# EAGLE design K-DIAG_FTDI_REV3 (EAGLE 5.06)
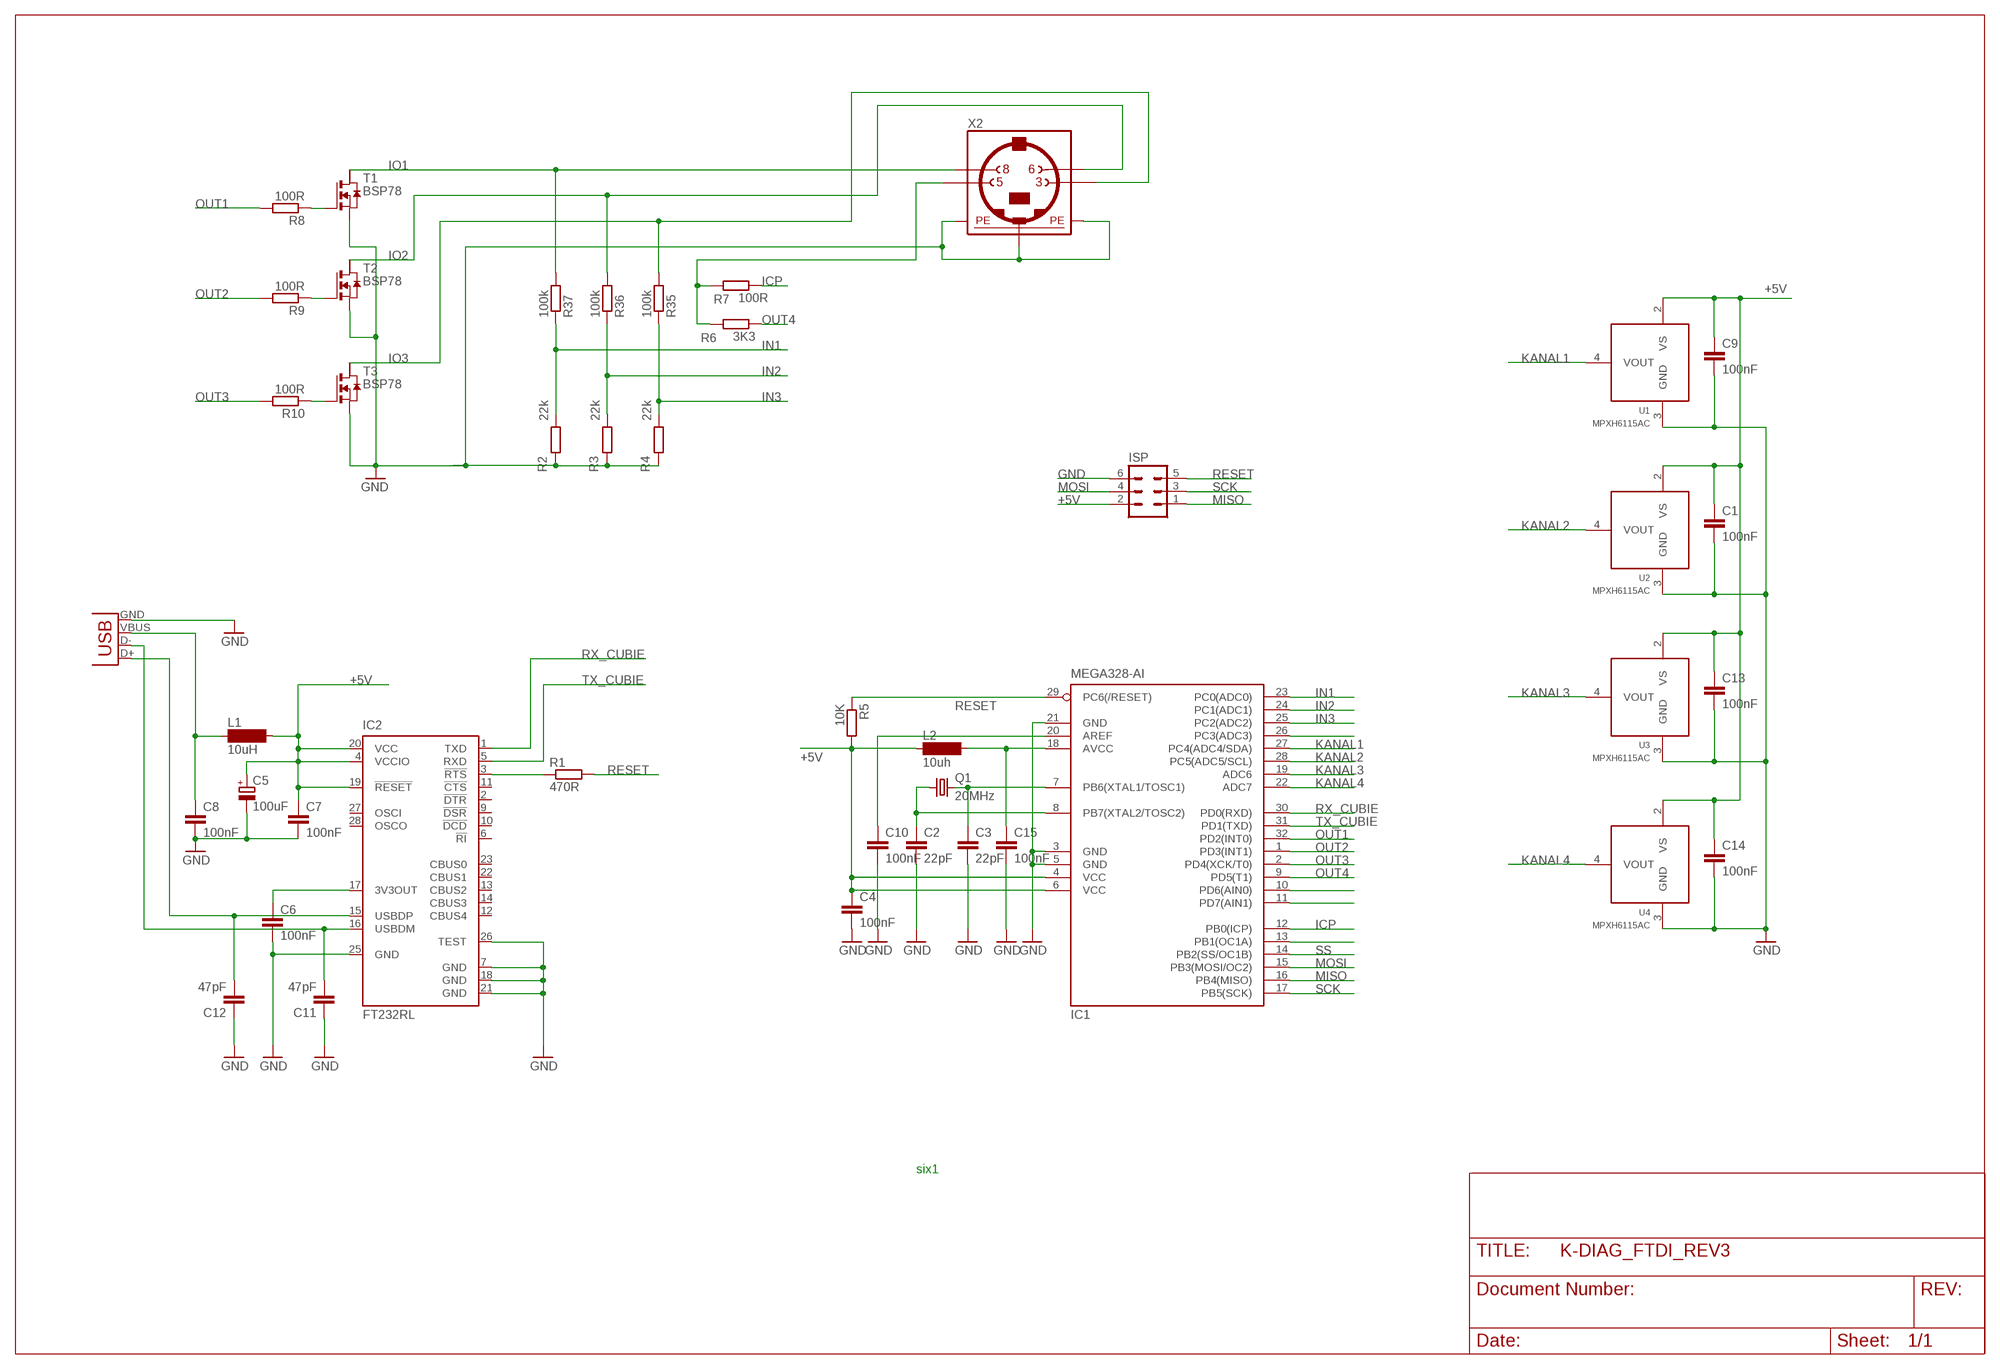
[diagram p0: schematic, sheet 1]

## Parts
C1  100nF  C-EUC0805  [C0805]
C2  22pF  C-EUC0805  [C0805]
C3  22pF  C-EUC0805  [C0805]
C4  100nF  C-EUC0805  [C0805]
C5  100uF  CPOL-EU153CLV-0605  [153CLV-0605]
C6  100nF  C-EUC0805  [C0805]
C7  100nF  C-EUC0805  [C0805]
C8  100nF  C-EUC0805  [C0805]
C9  100nF  C-EUC0805  [C0805]
C10  100nF  C-EUC0805  [C0805]
C11  47pF  C-EUC0805  [C0805]
C12  47pF  C-EUC0805  [C0805]
C13  100nF  C-EUC0805  [C0805]
C14  100nF  C-EUC0805  [C0805]
C15  100nF  C-EUC0805  [C0805]
IC1  MEGA328-AI  MEGA8-AI  [TQFP32-08]
IC2  FT232RL  [SSOP28]
ISP  ML6  [ML6]
L1  10uH  SM-1206  [SM-1206]
L2  10uh  SM-1206  [SM-1206]
Q1  20MHz  CRYSTAL10.5X4.8  [CRYSTAL-SMD-10.5X4.8-2PIN]
R1  470R  R-EU_R0805  [R0805]
R2  22k  R-EU_R0805  [R0805]
R3  22k  R-EU_R0805  [R0805]
R4  22k  R-EU_R0805  [R0805]
R5  10K  R-EU_R0805  [R0805]
R6  3K3  R-EU_R0805  [R0805]
R7  100R  R-EU_R0805  [R0805]
R8  100R  R-EU_R0805  [R0805]
R9  100R  R-EU_R0805  [R0805]
R10  100R  R-EU_R0805  [R0805]
R35  100k  R-EU_R0805  [R0805]
R36  100k  R-EU_R0805  [R0805]
R37  100k  R-EU_R0805  [R0805]
T1  BSP78  NMOSSOT223  [SOT223]
T2  BSP78  NMOSSOT223  [SOT223]
T3  BSP78  NMOSSOT223  [SOT223]
U1  MPXH6115AC  MPXH6400AC6T1  [SSOP8]
U2  MPXH6115AC  MPXH6400AC6T1  [SSOP8]
U3  MPXH6115AC  MPXH6400AC6T1  [SSOP8]
U4  MPXH6115AC  MPXH6400AC6T1  [SSOP8]
X1  USBPTH  [USB-B-PTH]
X2  MINI_DIN_4  [M_DIN4]

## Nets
+5V: C1.1 C4.1 C5.+ C7.1 C9.1 C13.1 C14.1 IC1.4(VCC) IC1.6(VCC) IC2.4(VCCIO) IC2.19(!RESET) IC2.20(VCC) ISP.2 L1.2 L2.1 R5.2 U1.2(VS) U2.2(VS) U3.2(VS) U4.2(VS)
GND: C1.2 C2.2 C3.2 C4.2 C5.- C6.2 C7.2 C8.2 C9.2 C10.2 C11.1 C12.1 C13.2 C14.2 C15.2 IC1.3(GND) IC1.5(GND) IC1.21(GND) IC2.7(GND) IC2.18(GND) IC2.21(GND) IC2.25(GND) IC2.26(TEST) ISP.6 R2.1 R3.1 R4.1 T1.3(S) T2.3(S) T3.3(S) U1.3(GND) U2.3(GND) U3.3(GND) U4.3(GND) X1.GND X2.SH1(PE1) X2.SH2(PE2) X2.SH3(PE3)
ICP: IC1.12(PB0(ICP)) R7.1
IN1: IC1.23(PC0(ADC0)) R2.2 R37.1
IN2: IC1.24(PC1(ADC1)) R3.2 R36.1
IN3: IC1.25(PC2(ADC2)) R4.2 R35.1
IN5: IC1.10(PD6(AIN0))
IN6: IC1.11(PD7(AIN1))
IN8: IC1.13(PB1(OC1A))
IO1: R37.2 T1.2(D) X2.8
IO2: R36.2 T2.2(D) X2.6
IO3: R35.2 T3.2(D) X2.3
KANAL1: IC1.27(PC4(ADC4/SDA)) U1.4(VOUT)
KANAL2: IC1.28(PC5(ADC5/SCL)) U2.4(VOUT)
KANAL3: IC1.19(ADC6) U3.4(VOUT)
KANAL4: IC1.22(ADC7) U4.4(VOUT)
MISO: IC1.16(PB4(MISO)) ISP.1
MOSI: IC1.15(PB3(MOSI/OC2)) ISP.4
N$1: C6.1 IC2.17(3V3OUT)
N$2: IC2.3(!RTS) R1.1
N$3: C8.1 L1.1 X1.VBUS
N$4: C10.1 IC1.20(AREF)
N$5: C15.1 IC1.18(AVCC) L2.2
N$6: C11.2 IC2.16(USBDM) X1.D-
N$7: R6.2 R7.2 X2.5
N$9: C2.1 IC1.8(PB7(XTAL2/TOSC2)) Q1.P$1
N$10: C3.1 IC1.7(PB6(XTAL1/TOSC1)) Q1.P$2
N$13: R8.1 T1.1(G)
N$19: C12.2 IC2.15(USBDP) X1.D+
N$33: R10.1 T3.1(G)
N$34: R9.1 T2.1(G)
OUT1: IC1.32(PD2(INT0)) R8.2
OUT2: IC1.1(PD3(INT1)) R9.2
OUT3: IC1.2(PD4(XCK/T0)) R10.2
OUT4: IC1.9(PD5(T1)) R6.1
REL4: IC1.26(PC3(ADC3))
RESET: IC1.29(PC6(/RESET)) ISP.5 R1.2 R5.1
RX_CUBIE: IC1.30(PD0(RXD)) IC2.1(TXD)
SCK: IC1.17(PB5(SCK)) ISP.3
SS: IC1.14(PB2(SS/OC1B))
TX_CUBIE: IC1.31(PD1(TXD)) IC2.5(RXD)
Unconnected: IC2.2(!DTR) IC2.6(!RI) IC2.9(!DSR) IC2.10(!DCD) IC2.11(!CTS) IC2.12(CBUS4) IC2.13(CBUS2) IC2.14(CBUS3) IC2.22(CBUS1) IC2.23(CBUS0) IC2.27(OSCI) IC2.28(OSCO) T1.4(D2) T2.4(D2) T3.4(D2) U1.1(NC) U1.5(NC) U1.6(NC) U1.7(NC) U1.8(NC) U2.1(NC) U2.5(NC) U2.6(NC) U2.7(NC) U2.8(NC) U3.1(NC) U3.5(NC) U3.6(NC) U3.7(NC) U3.8(NC) U4.1(NC) U4.5(NC) U4.6(NC) U4.7(NC) U4.8(NC)

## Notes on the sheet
- six1

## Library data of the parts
C1-C4 C6-C15 = rcl:C-EU: CAPACITOR, European symbol
C5 = rcl:CPOL-EU: POLARIZED CAPACITOR, European symbol
IC1 = atmel:MEGA8: MICROCONTROLLER 8 Kbytes FLASH, 1 kbytes SRAM, 512 bytes EEPROM, USART, 6-channel 10 bit ADC, 2-channel 8 bit ADC Pin compatible with Atmega48, ATMega88, ATMega168 Source: avr.lbr
IC2 = ftdichip:FT232R: Source: http://www.ftdichip.com/Documents/DataSheets/DS_FT232R_v104.pdf
ISP = con-harting-ml:ML6: HARTING
L1 L2 = inductor-neosid:SM-1206: INDUCTOR
Q1 = SparkFun:CRYSTAL: Crystals
R1-R10 R35-R37 = rcl:R-EU_: RESISTOR, European symbol
T1-T3 = zetex:NMOSSOT223: MOS FET
U1-U4 = mpxh6400:MPXH6400A
X1 = SparkFun:USB: USB Connectors USB-B-PTH is fully proven SKU : PRT-00139 USB-miniB is fully proven SKU : PRT-00587 USB-A-PCB is untested. USB-A-H is throughly reviewed, but untested. Spark Fun Electronics SKU : PRT-00437 USB-B-SMT is throughly reviewed, but untested. Needs silkscreen touching up. USB-A-S has not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
X2 = mini_din:MINI_DIN_4

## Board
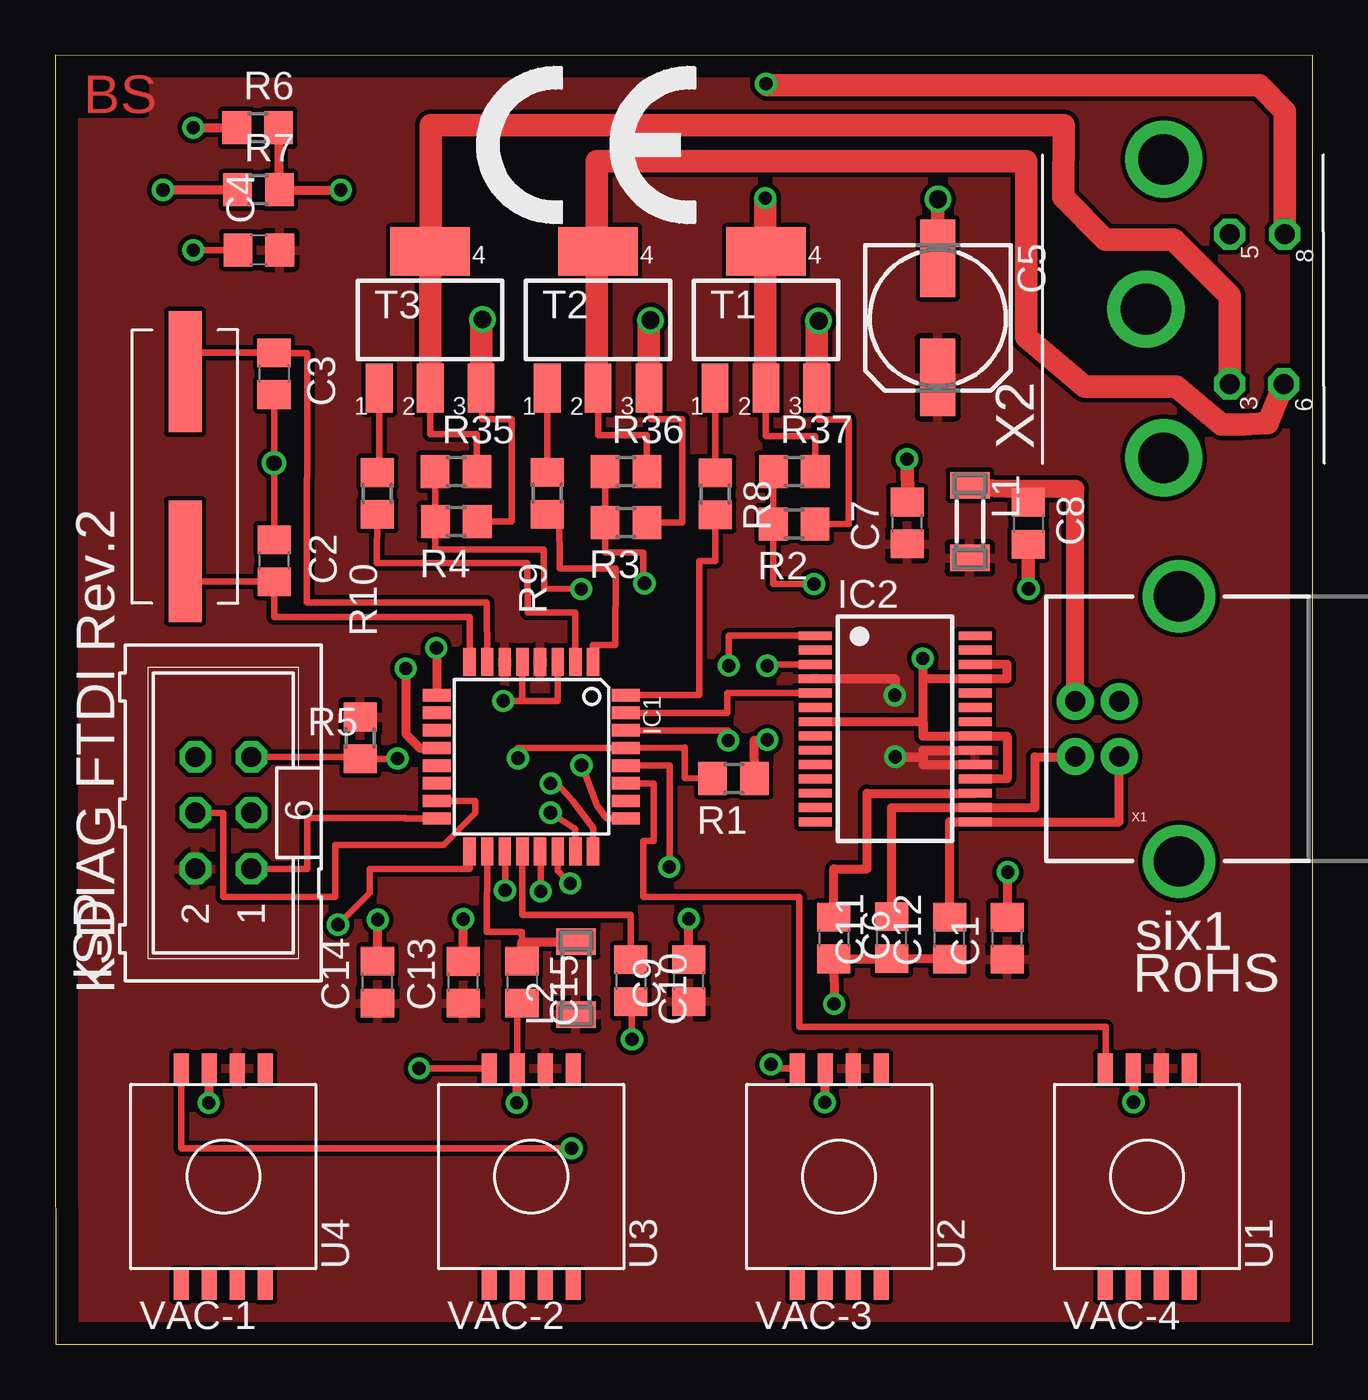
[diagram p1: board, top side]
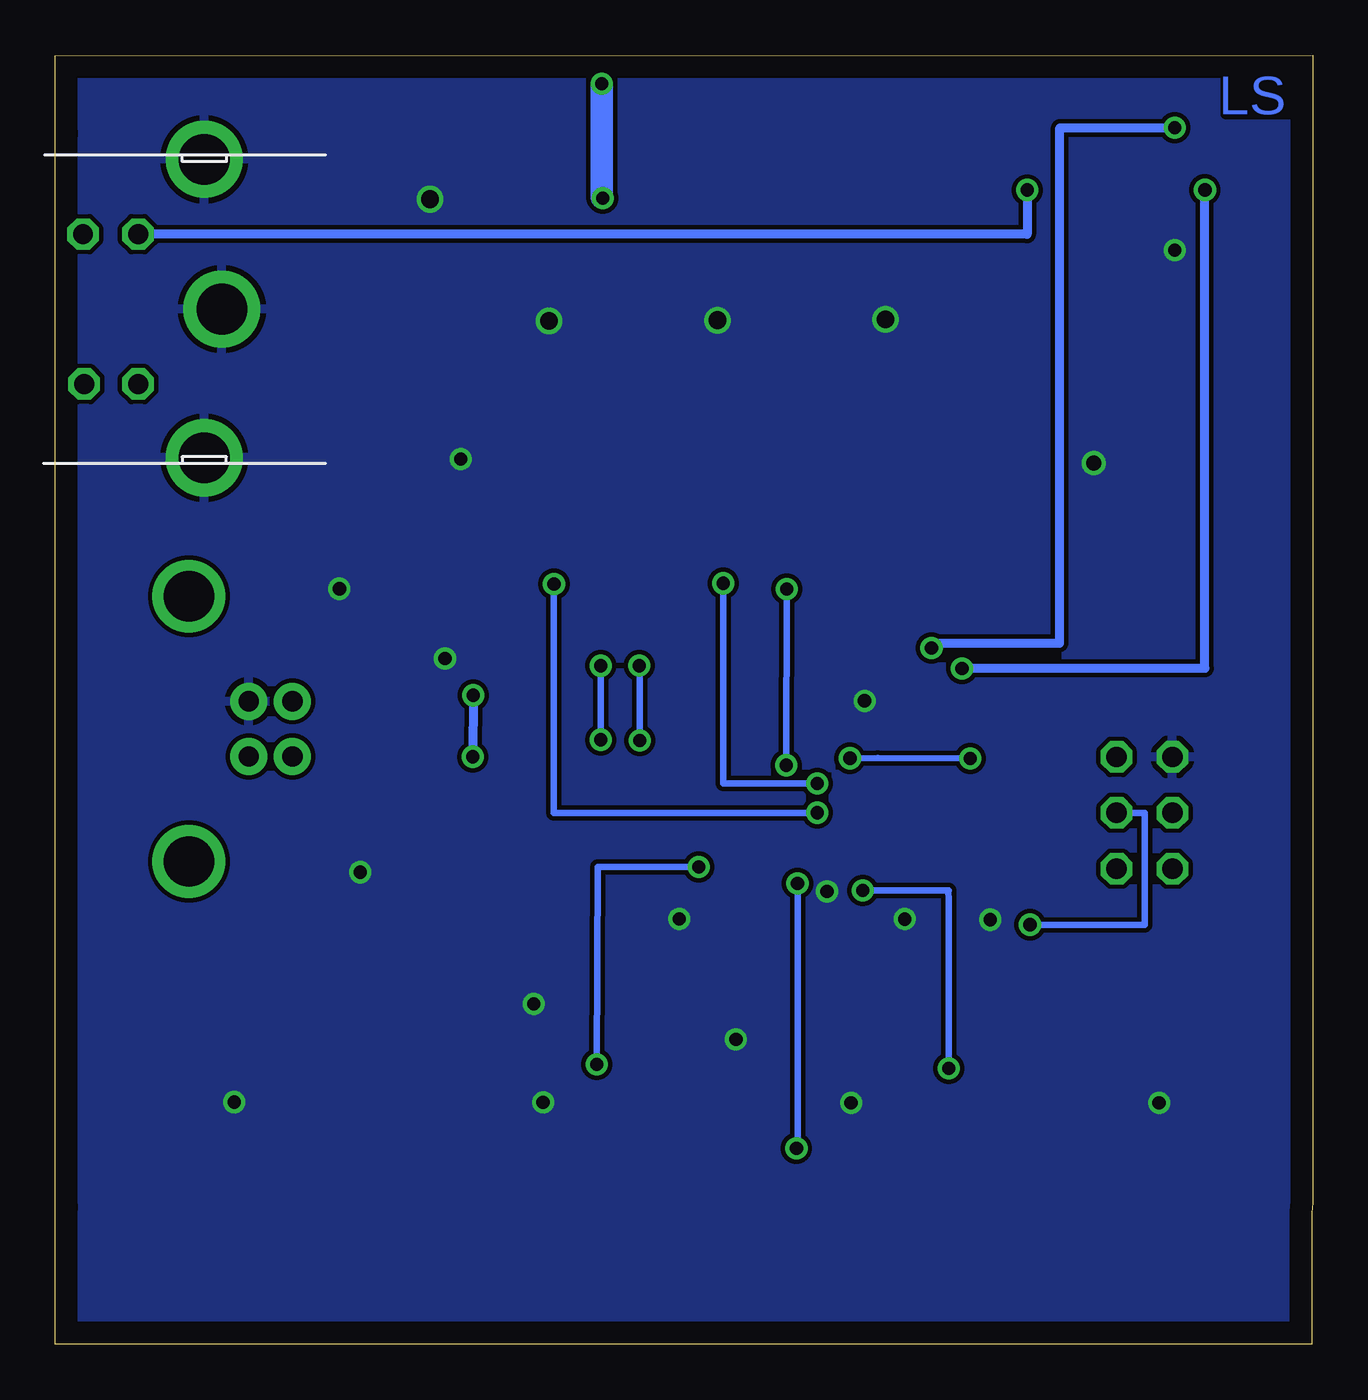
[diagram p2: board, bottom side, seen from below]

Size 57.06 x 58.52 mm. Coordinates in mm from the lower left corner, seen from the top.
Outline: 57.05,6.23 57.05,0 0.04,0 0.04,5.97 0,6.43 0,55.42 0,57.5 0,58.52 57.06,58.5 57.06,56.23 57.05,54.96 57.05,6.23
Outline: 57.05,6.23 57.05,6.23
Copper layers (1*16): Top 0.035mm / dielectric 1.5mm / Bottom 0.035mm
Design rules "default": minimum track width 10mil, minimum drill 24mil, track to track 8mil, track to pad 8mil, pad to pad 8mil, via to via 8mil, smd to smd 8mil, copper to edge 40mil, drill to drill 8mil, minimum pad ring 10mil, minimum via ring 8mil, stop-mask expansion 4mil, vias tented up to drill 0mil, thermal gap 10mil

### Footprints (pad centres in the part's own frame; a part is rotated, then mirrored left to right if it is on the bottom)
C0805 = smd 1.3 x 1.5: 1 -0.95,0; 2 0.95,0
153CLV-0605 = smd 3.5 x 1.6: + 2.7,0; - -2.7,0
TQFP32-08 = smd 1.27 x 0.559: 1 -4.293,2.8; 2 -4.293,2; 3 -4.293,1.2; 4 -4.293,0.4; 5 -4.293,-0.4; 6 -4.293,-1.2; 7 -4.293,-2; 8 -4.293,-2.8; 17 4.293,-2.8; 18 4.293,-2; 19 4.293,-1.2; 20 4.293,-0.4; 21 4.293,0.4; 22 4.293,1.2; 23 4.293,2; 24 4.293,2.8 | smd 0.559 x 1.27: 9 -2.8,-4.293; 10 -2,-4.293; 11 -1.2,-4.293; 12 -0.4,-4.293; 13 0.4,-4.293; 14 1.2,-4.293; 15 2,-4.293; 16 2.8,-4.293; 25 2.8,4.293; 26 2,4.293; 27 1.2,4.293; 28 0.4,4.293; 29 -0.4,4.293; 30 -1.2,4.293; 31 -2,4.293; 32 -2.8,4.293
SSOP28 = smd 0.4 x 1.5: 1 -4.225,-3.625; 2 -3.575,-3.625; 3 -2.925,-3.625; 4 -2.275,-3.625; 5 -1.625,-3.625; 6 -0.975,-3.625; 7 -0.325,-3.625; 8 0.325,-3.625; 9 0.975,-3.625; 10 1.625,-3.625; 11 2.275,-3.625; 12 2.925,-3.625; 13 3.575,-3.625; 14 4.225,-3.625; 15 4.225,3.625; 16 3.575,3.625; 17 2.925,3.625; 18 2.275,3.625; 19 1.625,3.625; 20 0.975,3.625; 21 0.325,3.625; 22 -0.325,3.625; 23 -0.975,3.625; 24 -1.625,3.625; 25 -2.275,3.625; 26 -2.925,3.625; 27 -3.575,3.625; 28 -4.225,3.625
ML6 = drill 0.914 octagon: 1 -2.54,-1.27; 2 -2.54,1.27; 3 0,-1.27; 4 0,1.27; 5 2.54,-1.27; 6 2.54,1.27
SM-1206 = smd 1.2 x 1.8: 1 -1.65,0; 2 1.65,0
CRYSTAL-SMD-10.5X4.8-2PIN = smd 5.5 x 1.5: P$1 -4.3,0; P$2 4.3,0
R0805 = smd 1.3 x 1.5: 1 -0.95,0; 2 0.95,0
SOT223 = smd 1.219 x 2.235: 1 -2.311,-3.099; 2 0,-3.099; 3 2.311,-3.099 | smd 3.6 x 2.2: 4 0,3.099
SSOP8 = smd 1.346 x 0.686: 1 4.915,-1.905; 2 4.915,-0.635; 3 4.915,0.635; 4 4.915,1.905; 5 -4.915,1.905; 6 -4.915,0.635; 7 -4.915,-0.635; 8 -4.915,-1.905
USB-B-PTH = drill 0.914 pad 1.676 round: D+ 0,1.25; D- 1.981,1.25; GND 0,-1.25; VBUS 1.981,-1.25 | drill 2.286 round: P$1 -2.718,-6.02; P$2 -2.718,6.02
M_DIN4 = drill 0.9 pad 1.422 octagon: 3 -3.4,-3.75; 5 3.4,-3.75; 6 -3.4,-6.2; 8 3.4,-6.25 | drill 2.3 pad 3.5 round: SH1 6.8,-0.75; SH2 0,0.05; SH3 -6.75,-0.75

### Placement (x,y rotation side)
C1  43.2,18.43 90 top
C2  9.95,35.57 90 top
C3  9.93,44.06 270 top
C4  9.24,49.67 180 top
C5  40.05,46.59 270 top
C6  35.33,18.45 270 top
C7  38.66,37.28 90 top
C8  44.16,37.27 270 top
C9  28.76,16.51 90 top
C10  26.12,16.51 270 top
C11  37.96,18.46 90 top
C12  40.58,18.44 90 top
C13  18.52,16.44 90 top
C14  14.63,16.44 90 top
C15  21.18,16.44 270 top
IC1  21.6,26.67 270 top
IC2  38.11,27.94 270 top
ISP  7.63,24.13 90 top
L1  41.5,37.35 270 top
L2  23.63,16.62 90 top
Q1  5.9,39.85 90 top
R1  30.78,25.69 180 top
R2  33.53,37.24 180 top
R3  25.9,37.31 180 top
R4  18.2,37.34 180 top
R5  13.85,27.53 90 top
R6  9.19,55.22 0 top
R7  9.22,52.4 0 top
R8  29.95,38.6 270 top
R9  22.32,38.63 270 top
R10  14.62,38.62 270 top
R35  18.19,39.61 0 top
R36  25.9,39.62 0 top
R37  33.54,39.62 0 top
T1  32.25,46.5 0 top
T2  24.63,46.5 0 top
T3  17.01,46.5 0 top
U1  49.54,7.62 90 top
U2  35.57,7.62 90 top
U3  21.6,7.62 90 top
U4  7.63,7.62 90 top
U$3  [CE_10.00]  19.06,50.8 0 top
X1  48.27,27.94 180 top
X2  49.54,46.99 90 top

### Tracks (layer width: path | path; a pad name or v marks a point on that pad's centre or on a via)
+5V  (via drill 0.6)
  Top 0.406: 39.38,26.96 IC2.20 | 39.38,26.96 39.38,26.32 IC2.19 | 39.38,26.96 39.38,26.67 v38.11,26.67 | v38.09,29.46 38.11,30.21 IC2.4
  Bottom 0.406: v38.09,29.46 v38.11,26.67
  pour Top: 64.78,60.33 29.22,60.33 27.93,60.22 -2.59,60.84 -2.53,16.51 -2.56,15.24 -2.56,-1.42 64.78,-1.27
GND  (via drill 0.6, 0.6 pad 0.81, 0.7, 0.8)
  Top 0.305: C3.2 v9.94,40 C2.2 | v22.04,20.56 22.04,22.38 IC1.21 | IC1.3 22.8,29.21 21.2,29.21 | 21.2,29.21 IC1.5 | v20.33,29.21 21.2,29.21 | C4.2 v6.27,49.67 | R4.1 20.72,37.34 20.72,42 19.39,42 v19.39,46.52 | R3.1 28.46,37.31 28.46,42 27.02,42 v27.02,46.49 | R2.1 36.02,37.24 36.02,41.98 34.65,41.98 v34.65,46.45 | C15.2 20.97,15.49 U3.3 | C10.2 26.17,15.56 v26.17,13.84
  Top 0.406: 39.38,27.61 IC2.21 43.19,27.61 43.19,25.66 IC2.18 | 39.38,30.21 IC2.25 43.19,30.21 43.19,30.86 IC2.26 | 39.38,27.61 39.38,30.21 | 39.38,27.61 39.38,28.27 IC2.7 | v35.34,15.46 35.33,17.4 C6.2 37.96,17.5 C11.1 40.58,17.51 C12.1 | 39.38,30.21 39.38,31.13 v39.37,31.13 | v43.22,21.43 43.22,19.38 C1.2 | v6.97,10.96 6.97,12.54 U4.3 | v20.95,10.96 20.95,12.54 U3.3 | v34.92,10.98 34.92,12.54 U2.3 | v48.93,10.99 48.93,12.54 U1.3 | C15.2 21.2,15.49 | v14.63,19.28 14.63,18.06 C14.2 | v18.52,19.3 C13.2 | v28.75,19.32 v28.76,19.32 C9.2
  Top 0.61: C7.2 38.69,38.18 v38.65,40.18 | C8.2 v44.16,34.29 | C5.- 40.05,50.14 v40.05,51.98
  Top 1.016: v34.65,46.45 34.57,46.37 T1.3 | v27.02,46.49 26.95,46.42 T2.3 | v19.39,46.52 19.33,46.46 T3.3
  pour Bottom: 64.78,60.33 26.68,60.33 26.66,60.22 27.89,60.15 -2.53,60.96 -2.56,16.51 -2.56,-1.34 64.78,-1.27
ICP  (via drill 0.6)
  Top 0.406: IC1.12 16.55,27.07 15.91,27.71 v15.91,30.68 | v4.89,52.4 R7.1
  Bottom 0.406: v15.91,30.68 4.89,30.68 v4.89,52.4
IN1  (via drill 0.6 pad 0.81)
  Top 0.305: IC1.23 23.6,23.4 v22.48,24.13 | v34.43,34.52 32.58,34.52 R2.2 R37.1
  Bottom 0.305: v22.48,24.13 34.43,24.13 v34.43,34.52
IN2  (via drill 0.6 pad 0.81)
  Top 0.305: IC1.24 24.42,23.45 23.49,24.68 22.82,25.44 v22.48,25.47 | v26.74,34.54 26.68,34.54 26.68,35.94 24.95,35.94 R3.2 R36.1
  Bottom 0.305: v22.48,25.47 26.74,25.47 v26.74,34.54
IN3  (via drill 0.6 pad 0.81)
  Top 0.305: IC1.25 25.04,23.87 24.61,24.43 v23.88,26.29 | v23.87,34.29 22.19,34.32 22.17,36.07 17.26,36.07 R4.2 R35.1
  Bottom 0.305: v23.88,26.29 v23.87,34.29
IO1  (via drill 0.6)
  Top 0.305: T1.2 32.25,41.22 34.49,41.22 R37.2
  Top 1.016: X2.8 55.79,55.98 54.62,57.15 32.33,57.15 v32.26,57.22 | v32.22,52.02 32.22,43.44 T1.2
  Bottom 1.016: v32.26,57.22 32.26,52.06 v32.22,52.02
IO2
  Top 0.305: T2.2 24.63,41.27 26.85,41.27 R36.2
  Top 1.016: X2.6 55.03,41.81 53.86,41.74 52.94,41.74 50.87,43.47 46.71,43.47 44.06,45.72 44.06,53.7 24.59,53.7 24.59,43.4 T2.2
IO3
  Top 0.305: T3.2 17.01,41.31 19.14,41.31 R35.2
  Top 1.016: X2.3 53.29,47.61 50.75,50.15 47.66,50.15 45.73,52.07 45.77,55.33 17.05,55.33 T3.2
KANAL1
  Top 0.305: IC1.27 27.17,25.47 27.17,22.86 26.68,22.86 26.68,20.32 33.77,20.32 33.77,14.41 47.68,14.41 47.68,12.56 U1.4
KANAL2  (via drill 0.6)
  Top 0.305: IC1.28 27.88,26.27 27.88,21.69 v27.86,21.67 | v32.48,12.71 32.49,12.53 U2.4
  Bottom 0.305: v27.86,21.67 32.45,21.67 v32.48,12.71
KANAL3  (via drill 0.6, 0.6 pad 0.81)
  Top 0.305: IC1.19 v20.42,20.61 | v16.52,12.53 U3.4
  Bottom 0.305: v20.42,20.61 16.52,20.61 16.53,20.6 16.52,20.16 16.52,13.97 v16.52,12.53
KANAL4  (via drill 0.6)
  Top 0.305: IC1.22 22.8,21.5 v23.38,20.93 | v23.43,8.9 5.73,8.9 U4.4
  Bottom 0.305: v23.38,20.93 23.38,8.95 v23.43,8.9
MISO
  Top 0.305: ISP.1 11.44,21.59 11.44,23.89 15.89,23.89 15.89,23.87 IC1.16 17.29,23.85
MOSI
  Top 0.305: IC1.15 19.06,24.67 19.06,24.13 17.64,22.66 16.55,22.68 12.71,22.68 12.71,20.32 7.63,20.32 7.63,24.13 ISP.4
N$1
  Top 0.406: IC2.17 36.84,25.02 36.84,21.59 35.33,21.59 C6.1
N$2  (via drill 0.6)
  Top 0.305: 32.31,30.86 IC2.3
  Top 0.406: v32.31,30.81 32.31,30.86 | v32.31,27.44 31.73,27.43 R1.1
  Bottom 0.305: v32.31,27.44 v32.31,30.81
N$3
  Top 0.61: 43.19,38.83 43.2,38.83 | C8.1 44.16,38.86 41.94,38.86
  Top 0.813: X1.VBUS 46.29,38.83 43.19,38.83 41.94,38.86 L1.1
N$4
  Top 0.305: C10.1 26.12,19.5 21.2,19.5 IC1.20
N$5
  Top 0.305: IC1.18 19.59,18.72 21.17,18.72 21.19,18.27
  Top 0.406: C15.1 21.18,18.27 | 21.18,18.27 L2.2 | 21.18,18.27 21.19,18.27
N$6
  Top 0.406: X1.D- 46.29,26.67 44.46,26.67 44.46,24.36 IC2.16 37.96,24.36 C11.2
N$7  (via drill 0.6)
  Top 0.406: R6.2 10.18,55.22 R7.2 v12.96,52.4
  Bottom 0.406: X2.5 12.96,50.39 v12.96,52.4
N$9
  Top 0.305: Q1.P$1 5.9,34.62 C2.1 9.95,33.02 18.8,33.02 IC1.8
N$10
  Top 0.305: C3.1 5.9,45.01 Q1.P$2 | 9.93,44.99 11.44,44.99 11.42,33.68 19.58,33.68 IC1.7
  Top 0.406: 9.93,44.99 C3.1
N$13
  Top 0.305: T1.1 29.94,39.55 R8.1
N$19
  Top 0.406: 48.27,26.67 X1.D+ 48.27,23.71 IC2.15 40.58,23.71 C12.2
N$33
  Top 0.305: T3.1 14.7,39.57 R10.1
N$34
  Top 0.305: R9.1 T2.1 | R9.1
OUT1
  Top 0.305: IC1.32 29.22,29.47 29.22,35.56 29.95,35.56 R8.2
OUT2
  Top 0.305: R9.2 22.87,37.68 22.9,35.2 25.44,35.2 25.41,31.75 24.4,31.75 IC1.1
OUT3
  Top 0.305: R10.2 14.6,35.48 21.43,35.48 21.45,33.21 23.61,33.21 IC1.2
OUT4  (via drill 0.6)
  Top 0.406: v17.3,31.6 v17.31,31.6 IC1.9 | v6.26,55.22 R6.1
  Bottom 0.406: v6.26,55.22 11.47,55.22 11.49,31.82 17.3,31.82 v17.3,31.6
RESET  (via drill 0.6 pad 0.81)
  Top 0.305: R1.2 28.56,25.71 28.56,27.09 IC1.29 21,27.07 v21,26.6 | ISP.5 14.13,26.67 R5.1 15.74,26.58 v15.54,26.6
  Bottom 0.305: v15.54,26.6 19.73,26.62 v21,26.6
RX_CUBIE  (via drill 0.6)
  Top 0.305: IC2.1 30.56,32.16 v30.56,30.81 | v30.54,27.41 30.54,27.87 IC1.30
  Bottom 0.305: v30.54,27.41 30.54,30.7
  Bottom 0.406: 30.54,30.7 v30.56,30.81
SCK  (via drill 0.6 pad 0.81)
  Top 0.305: v12.83,19.05 14.27,20.48 14.27,21.59 18.8,21.59 IC1.17
  Bottom 0.305: ISP.3 7.63,24.13 7.63,19.05 v12.83,19.05
TX_CUBIE
  Top 0.305: IC1.31 30.49,28.67 30.49,29.57 IC2.5

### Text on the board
Top: BS
Bottom: LS
tPlace: DIAG-3 | DIAG-2 | DIAG-1 | GND | six1 | K-DIAG FTDI Rev.2 | RoHS | VAC-1 | VAC-2 | VAC-3 | VAC-4
tNames: CleverGate_IQ-III_REV-2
